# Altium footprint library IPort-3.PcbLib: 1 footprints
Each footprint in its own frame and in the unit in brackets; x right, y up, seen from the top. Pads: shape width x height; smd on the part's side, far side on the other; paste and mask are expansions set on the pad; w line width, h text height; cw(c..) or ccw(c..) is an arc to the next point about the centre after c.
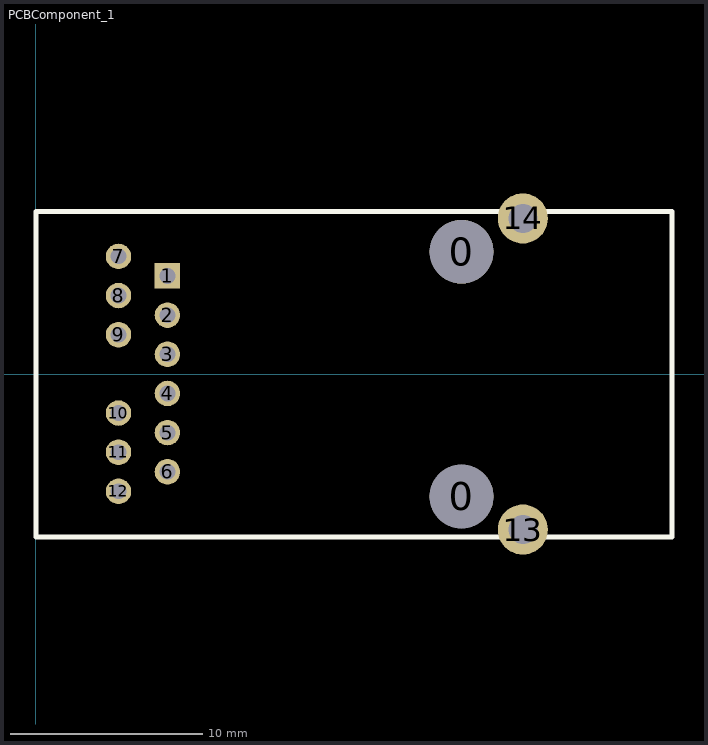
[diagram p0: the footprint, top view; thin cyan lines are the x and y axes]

## PCBComponent_1 [mil]
pads (16):
  round 129.92 hole 129.92: 0(869.68,-250) 0(869.68,250)
  rect 52x52 hole 32: 1(268.88,200.5)
  round 52 hole 32: 2(268.88,120.5) 5(268.88,-119.5) 7(168.88,240.5) 8(168.88,160.5) 9(168.88,80.5) 12(168.88,-239.5)
  round 52 hole 32 mask+2: 3(268.88,40.5) 4(268.88,-39.5) 6(268.88,-199.5) 10(168.88,-79.5) 11(168.88,-159.5)
  round 102.36 hole 59.06: 13(994.88,-317.52) 14(994.88,318)
Top Overlay:
  lines w10: 0,-332.5 1300,-332.5 1300,307.5 1300,332.5 0,332.5 0,-332.5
